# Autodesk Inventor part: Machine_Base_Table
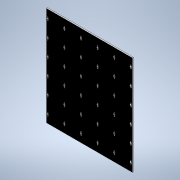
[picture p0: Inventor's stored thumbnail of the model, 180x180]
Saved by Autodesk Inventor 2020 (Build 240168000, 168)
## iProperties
Created: 2020-02
Part Number: Machine_Base_Table
Material: Generic
Document SubType Name: Modeling
Designer: mmg
Density: 1 g/cm^3
Appearance: Default
Author: mmg
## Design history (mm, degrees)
sketch "Sketch1"
  geometry: L1 (0, 0)-(860, 0); L2 (860, 0)-(860, 990); L3 (860, 990)-(0, 990); L4 (0, 990)-(0, 0)
  constraints: 8 end point, 2 parallel, 1 horizontal, 1 perpendicular
  dimensions: "d0" = 860 distance of L3.end L2.end; "d1" = 990 distance of L2.end L1.end
extrude "Extrusion1" new body sketch "Sketch1" distance "d2" = 12; taper "d3" = 0 deg
sketch "Sketch2"
  geometry: L1 (10, 64.5)-(10, 71.07); L2 (19, 64.5)-(19, 71.07); L3 (10, 95.5)-(10, 88.93); L4 (19, 95.5)-(19, 88.93); L5 (0, 990)-(0, 0) reference; L6 (0, 0)-(860, 0) reference; A1 r 4.5 centre (14.5, 95.5) between (19, 95.5) and (10, 95.5); A2 r 4.5 centre (14.5, 64.5) between (10, 64.5) and (19, 64.5); A3 r 10 centre (14.5, 80) between (10, 88.93) and (10, 71.07); A4 r 10 centre (14.5, 80) between (19, 71.07) and (19, 88.93)
  constraints: 8 end point, 8 point on circle, 4 centre point, 4 point on line, 1 vertical
  dimensions: "d5" = 9 diameter of A1; "d6" = 9 diameter of A2; "d7" = 9 distance between parallel lines of L2 L1; "d8" = 31 distance of A2.centre A1.centre; "d9" = 15.5 distance of A2.centre A3.centre; "d10" = 10 radius of A3; "d11" = 10 radius of A4; "d12" = 6.56971 distance of L2.start L2.end; "d13" = 10 distance between parallel lines of L5 L1; "d14" = 64.5 distance from line of L6 A2.centre
extrude "Extrusion2" cut sketch "Sketch2" distance "d15" = 12; taper "d16" = 0 deg
body "Solid1"
pattern_linear "Rectangular Pattern1" dims "d19" = 165, "d22" = 166
